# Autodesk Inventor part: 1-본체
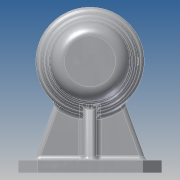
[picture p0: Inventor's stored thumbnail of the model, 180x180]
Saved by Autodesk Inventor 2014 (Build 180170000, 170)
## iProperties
Created: 2017-09
Part Number: 1-본체
Material: 알루미늄 6061
Document SubType Name: Modeling
Designer: kb542-22
Density: 2.71 g/cm^3
Appearance: 알루미늄 - 평지
Mass: 698.012 g
Surface Area: 708.911 cm^2
Volume: 257.569 cm^3
Author: kb542-22
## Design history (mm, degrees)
sketch "스케치1"
  geometry: L1 (56, 0)-(-56, 0); L2 (56, 21)-(41, 21); L3 (41, 21)-(41, 24); L4 (41, 24)-(-13, 24); L5 (-13, 24)-(-13, 21); L6 (-13, 21)-(-25, 21); L7 (-25, 21)-(-25, 17.5); L8 (-25, 17.5)-(-43, 17.5); L9 (-43, 17.5)-(-43, 16); L10 (-43, 16)-(-47, 16); L11 (-47, 16)-(-47, 10.5); L12 (-47, 10.5)-(-50, 10.5); L13 (-50, 10.5)-(-50, 0); L14 (-56, 0)-(-56, 25); L15 (-56, 25)-(-32.5, 25); L16 (-31, 27)-(-13.25, 27); L17 (-11, 30)-(25, 30); L18 (28, 34)-(56, 34); L19 (56, 34)-(56, 21); L20 (28, 34)-(28, 30); L21 (28, 30)-(25, 30); L22 (-13.25, 27)-(-11, 27); L23 (-11, 27)-(-11, 30); L24 (-32.5, 25)-(-31, 25); L25 (-31, 25)-(-31, 27); 2 further points
  constraints: 50 end point, 16 parallel, 7 perpendicular, 1 coincident, 1 collinear, 1 horizontal, 1 midpoint, 1 point on line, 1 vertical alignment
  dimensions: "d0" = 42 diameter of L2 L1; "d1" = 48 diameter of L4 L1; "d2" = 42 diameter of L6 L1; "d3" = 35 diameter of L8 L1; "d4" = 32 diameter of L10 L1; "d5" = 21 diameter of L12 L1; "d6" = 50 diameter of L15 L1; "d7" = 54 diameter of L16.start L1; "d8" = 60 diameter of L17.start L1; "d9" = 68 diameter of L18 L1; "d10" = 15 distance of L2.start L2.end; "d11" = 54 distance of L3.end L4.end; "d12" = 12 distance of L5.end L6.end; "d13" = 18 distance of L7.end L8.end; "d14" = 4 distance of L9.end L10.end; "d15" = 3 distance of L11.end L12.end; "d16" = 112 distance between parallel lines of L19 L14; "d75" = 25 distance between parallel lines of L25 L14; "d76" = 45 distance between parallel lines of L23 L14; "d77" = 84 distance between parallel lines of L20 L14
revolve "회전1" sketch "스케치1" stored, may be unused: angle "d22" = 90 deg
node "작업 평면1"
sketch "스케치2"
  geometry: L1 (-56, 45)-(56, 45); L2 (56, 45)-(56, -45); L3 (56, -45)-(-56, -45); L4 (-56, -45)-(-56, 45); L5 (56, -34)-(56, 34) reference; 2 further points
  constraints: 8 end point, 2 parallel, 1 collinear, 1 horizontal, 1 horizontal alignment, 1 midpoint, 1 perpendicular
  dimensions: "d24" = 112 distance of L1.start L1.end; "d25" = 90 distance of L1.end L2.end
extrude "돌출1" join sketch "스케치2" distance "d26" = 8; taper "d27" = 0 deg
node "작업 평면2"
sketch "스케치3"
  geometry: L1 (45, -62)-(-45, -62) reference; L2 (21.9, -26.008)-(35, -62); L3 (-21.9, -26.008)-(-35, -62); L4 (45, -70)-(45, -62) reference; L5 (-45, -70)-(-45, -62) reference; A1 r 34 centre (0, 0) between (21.9, -26.008) and (-21.9, -26.008) reference; 1 further point
  constraints: 4 end point, 2 point on circle, 2 point on line
  dimensions: "d30" = 110 deg angle of L1 L2; "d31" = 110 deg angle of L1 L3; "d32" = 10 distance from line of L4 L2.end; "d33" = 10 distance from line of L5 L3.end
extrude "돌출2" join sketch "스케치3" distance "d34" = 8; taper "d35" = 0 deg
sketch "스케치4"
  geometry: L1 (56, -25)-(31, -25) reference; L2 (31, -27)-(11, -27) reference; L3 (11, -30)-(-28, -30) reference; L4 (-28, -34)-(-48, -34) reference; L5 (-56, -62)-(56, -62) reference; L6 (24.622, -27)-(34, -62); L7 (56, -70)-(56, -62) reference; 1 further point
  constraints: 2 end point, 2 point on line
  dimensions: "d36" = 22 distance from line of L7 L6.end; "d37" = 105 deg angle of L5 L6
feature "리브1" sketch "스케치4" dims "d38" = 1, "d39" = 8, "d40" = 0, "d41" = 0, "d42" = 1, "d43" = 1
sketch "스케치5"
  geometry: L1 (-8, 80)-(-8, 90) reference; L2 (-70, 45)-(-96, 45); L3 (-70, 45)-(-57, 22.483); C1 r 21 at (-70, 45) reference; A1 r 26 centre (-70, 45) between (-96, 45) and (-57, 22.483); 1 further point
  constraints: 4 end point, 2 coincident, 2 point on circle, 1 centre point, 1 perpendicular
  dimensions: "d44" = 52 diameter of A1; "d45" = 120 deg angle of L2 L3
hole "구멍1" sketch "스케치5" at (-96, 45) diameter "d46" = 3.242; stored, may be unused: countersink angle "d50" = 90 deg, drill point angle "d52" = 118 deg; dims "d47" = 8, "d48" = 4, "d49" = 2, "d51" = 11
node "작업 평면3"
sketch "스케치6"
  geometry: L1 (29.5, -26.008)-(29.5, 34) reference; 2 further points
  constraints: 1 horizontal alignment, 1 other
  dimensions: "d57" = 48 distance from line of point (-18.5, 0) L1
feature "엠보싱1" sketch "스케치6" dims "d0" = 42, "d1" = 48, "d2" = 42, "d3" = 35, "d4" = 32, "d5" = 21, "d6" = 50, "d7" = 54, "d8" = 60, "d9" = 68, "d10" = 15, "d11" = 54, "d12" = 12, "d13" = 18, "d14" = 4, "d15" = 3, "d16" = 112, "d59" = 0.5, "d60" = 0, "d75" = 25, "d76" = 45, "d77" = 84
sketch "스케치7"
  geometry: L1 (48, -4)-(-34, -4) reference; L2 (56, -45)-(56, -35) reference; L3 (32, -34)-(20, -34); L4 (32, -30)-(20, -30); L5 (20, -38)-(32, -38); L6 (-20, -34)-(-32, -34); L7 (-20, -30)-(-32, -30); L8 (-32, -38)-(-20, -38); L9 (56, 45)-(56, -45) reference; L10 (-56, -45)-(-56, 45) reference; L11 (56, 0)-(-56, 0); A1 r 4 centre (32, -34) between (32, -38) and (32, -30); A2 r 4 centre (20, -34) between (20, -30) and (20, -38); A3 r 4 centre (-20, -34) between (-20, -38) and (-20, -30); A4 r 4 centre (-32, -34) between (-32, -30) and (-32, -38); 3 further points
  constraints: 18 end point, 8 point on circle, 8 tangent, 4 centre point, 4 midpoint, 4 parallel, 1 collinear
  dimensions: "d61" = 12 distance of L3.end L3.start; "d62" = 24 distance from line of L2 L3.start; "d63" = 4 radius of A2; "d64" = 12 distance of L6.end L6.start; "d65" = 40 distance of L3.end L6.start; "d67" = 4 radius of A3; "d68" = 34 distance from line of L11 L6.end
extrude "돌출3" cut sketch "스케치7" stored distance "d69" = 8; taper "d70" = 0 deg
chamfer "모따기1" distance "d71" = 12; stored, may be unused: second distance "d72" = 2, angle "d73" = 45 deg
fillet "모깎기1" dims "d74" = 9
fillet "모깎기2" dims "d78" = 3
fillet "모깎기3" dims "d79" = 3
fillet "모깎기4" dims "d80" = 3
fillet "모깎기5" dims "d81" = 3
fillet "모깎기6" dims "d82" = 3
fillet "모깎기7" dims "d83" = 0.3
chamfer "모따기2" distance "d84" = 1; stored, may be unused: second distance "d85" = 2, angle "d86" = 45 deg
node "솔리드1"
pattern_circular "원형 패턴1" dims angle "d54" = 360 deg
mirror "대칭1"
other parameters: "d28" = 48
